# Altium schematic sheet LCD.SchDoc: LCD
size A4; Date: Not used; ApprovedBy: Not used; CheckedBy: Not used; Author: Not used; CompanyName: STMicroelectronics; DrawnBy: Not used; Engineer: Not used; Organization: Not used; Address1: Not used; Address2: Not used; Address3: Not used; Address4: Not used; DocumentNumber: Not used; Revision: Not used; SheetNumber: 13; SheetTotal: 23
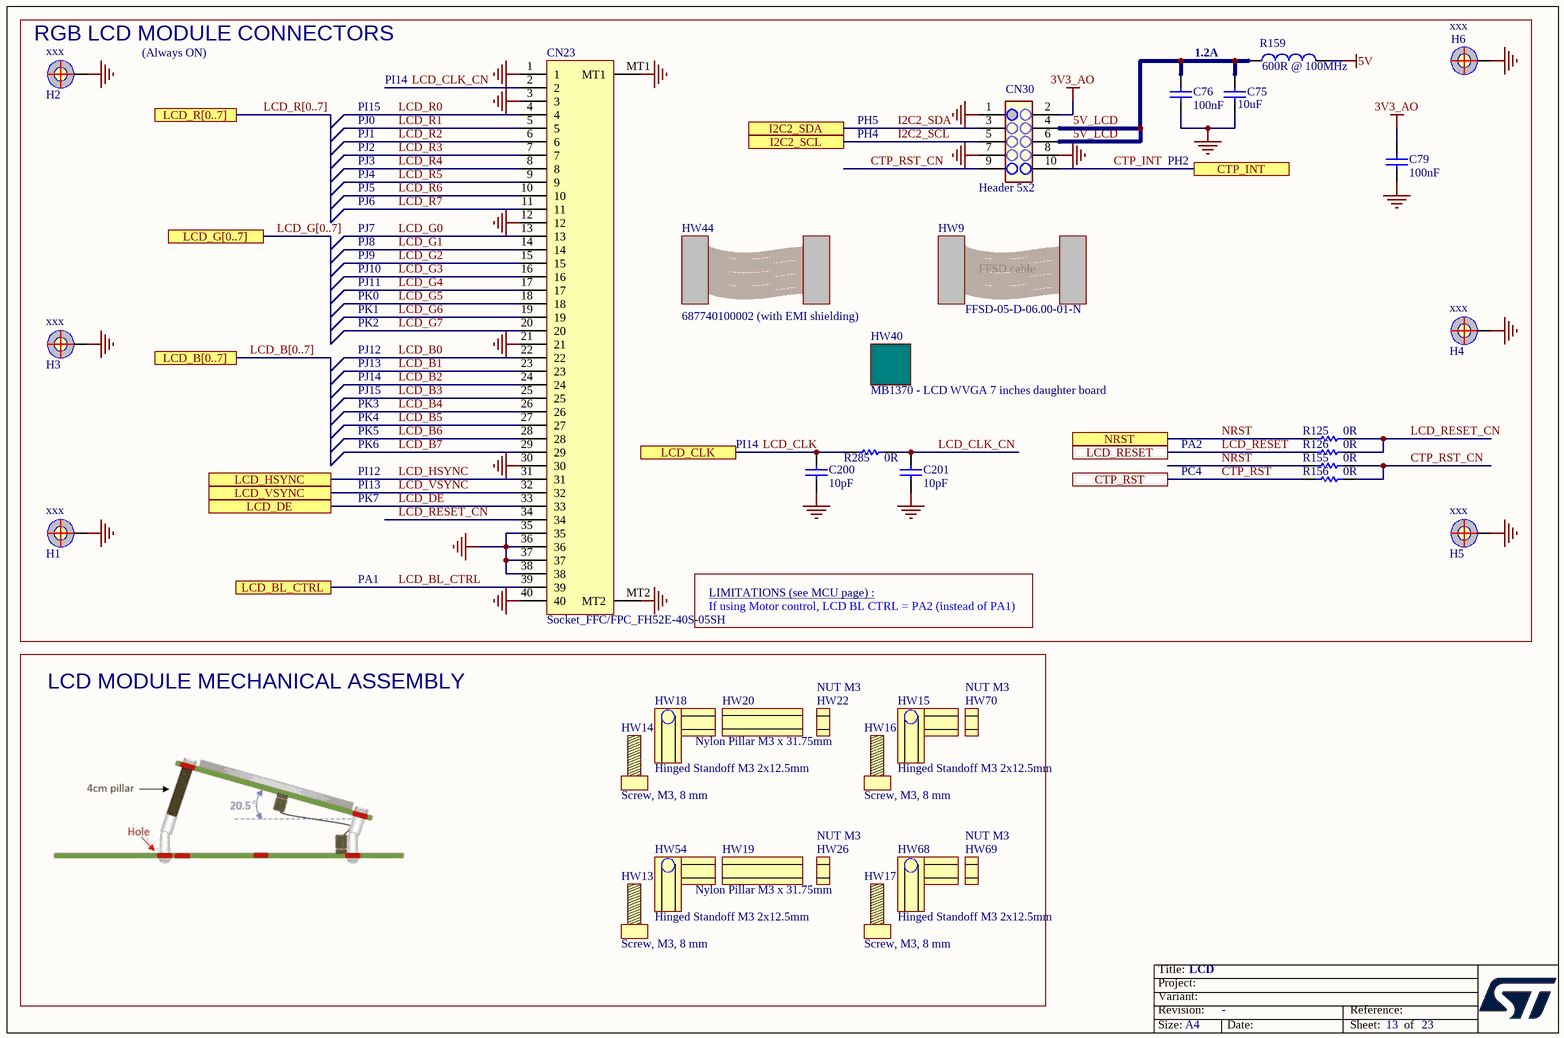
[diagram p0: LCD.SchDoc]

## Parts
C75  value 10uF  [C0805]  (hidden comment: Capacitor)
C76  value 100nF  [C0402]  (hidden comment: Capacitor)
C79  value 100nF  [C0402]  (hidden comment: Capacitor)
C200  value 10pF  [C0402]  (hidden comment: Capacitor)
C201  value 10pF  [C0402]  (hidden comment: Capacitor)
CN23  value Socket_FFC/FPC_FH52E-40S-05SH  [CON_HRS_FH52E-40S-05SH]  (hidden comment: FH52E-40S-0.5SH)
CN30  value Header 5x2  [CON_SAMTEC_FTSH-105-01-L-DV-K]  (hidden comment: Header 5x2 Generic)
H1  value xxx  [PTH_M1261-3005-N_3P5X6_M3_H14]  (hidden comment: POSITION HOLE)  (no BOM)
H2  value xxx  [PTH_M1261-3005-N_3P5X6_M3_H14]  (hidden comment: POSITION HOLE)  (no BOM)
H3  value xxx  [PTH_M1261-3005-N_3P5X6_M3_H14]  (hidden comment: POSITION HOLE)  (no BOM)
H4  value xxx  [PTH_M1261-3005-N_3P5X6_M3_H14]  (hidden comment: POSITION HOLE)  (no BOM)
H5  value xxx  [PTH_M1261-3005-N_3P5X6_M3_H14]  (hidden comment: POSITION HOLE)  (no BOM)
H6  value xxx  [PTH_M1261-3005-N_3P5X6_M3_H14]  (hidden comment: POSITION HOLE)  (no BOM)
HW9  value FFSD-05-D-06.00-01-N  (hidden comment: FFSD05_CABLE)  (mechanical)
HW13  value Screw, M3, 8 mm  (hidden comment: SCREW)  (no BOM)
HW14  value Screw, M3, 8 mm  (hidden comment: SCREW)  (no BOM)
HW15  value Hinged Standoff M3 2x12.5mm  (hidden comment: Hinged_Standoff)  (no BOM)
HW16  value Screw, M3, 8 mm  (hidden comment: SCREW)  (no BOM)
HW17  value Screw, M3, 8 mm  (hidden comment: SCREW)  (no BOM)
HW18  value Hinged Standoff M3 2x12.5mm  (hidden comment: Hinged_Standoff)  (no BOM)
HW19  value Nylon Pillar M3 x 31.75mm  (hidden comment: PILLAR)  (no BOM)
HW20  value Nylon Pillar M3 x 31.75mm  (hidden comment: PILLAR)  (no BOM)
HW22  value NUT M3  (hidden comment: NUT)  (no BOM)
HW26  value NUT M3  (hidden comment: NUT)  (no BOM)
HW40  value MB1370 - LCD WVGA 7 inches daughter board  [LCD_DRAWING_ROCKTEK_RK070ER9427L]  (hidden comment: Daughter_Board)
HW44  value 687740100002 (with EMI shielding)  (hidden comment: CABLE)  (mechanical)
HW54  value Hinged Standoff M3 2x12.5mm  (hidden comment: Hinged_Standoff)  (no BOM)
HW68  value Hinged Standoff M3 2x12.5mm  (hidden comment: Hinged_Standoff)  (no BOM)
HW69  value NUT M3  (hidden comment: NUT)  (no BOM)
HW70  value NUT M3  (hidden comment: NUT)  (no BOM)
R125  value 0R  [R0603]  (hidden comment: Resistor)
R126  value 0R  [R0603]  (hidden comment: Resistor)
R155  value 0R  [R0603]  (hidden comment: Resistor)
R156  value 0R  [R0603]  (hidden comment: Resistor)
R159  value 600R @ 100MHz  [IND_0603_H0P8]  (hidden comment: Inductor)
R285  value 0R  [R0603]  (hidden comment: Resistor)

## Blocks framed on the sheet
RGB LCD MODULE CONNECTORS: C75 C76 C79 C200 C201 CN23 CN30 H1-H6 HW9 HW40 HW44 R125 R126 R155 R156 R159 R285
LCD MODULE MECHANICAL ASSEMBLY: HW13-HW20 HW22 HW26 HW54 HW68-HW70

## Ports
CTP_INT, CTP_RST, I2C2_SCL, I2C2_SDA, LCD_B[0..7], LCD_BL_CTRL, LCD_CLK, LCD_DE, LCD_G[0..7], LCD_HSYNC, LCD_R[0..7], LCD_RESET, LCD_VSYNC, NRST

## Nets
3V3_AO: C79.2 CN30.2
5V: R159.2
GND: C75.1 C76.2 C79.1 C200.1 C201.1 CN23.1 CN23.3 CN23.12 CN23.21 CN23.30 CN23.35 CN23.36 CN23.37 CN23.38 CN23.40 CN23.MT1 CN23.MT2 CN30.1 CN30.7 CN30.8 H1.1 H2.1 H3.1 H4.1 H5.1 H6.1
5V_LCD: C75.2 C76.1 CN30.4 CN30.6 R159.1
CTP_INT: CN30.10 ; port CTP_INT
CTP_RST: R156.1 ; port CTP_RST
CTP_RST_CN: CN30.9 R155.2 R156.2
I2C2_SCL: CN30.5 ; port I2C2_SCL
I2C2_SDA: CN30.3 ; port I2C2_SDA
LCD_B0: CN23.22
LCD_B1: CN23.23
LCD_B2: CN23.24
LCD_B3: CN23.25
LCD_B4: CN23.26
LCD_B5: CN23.27
LCD_B6: CN23.28
LCD_B7: CN23.29
LCD_BL_CTRL: CN23.39 ; port LCD_BL_CTRL
LCD_CLK: C200.2 R285.1 ; port LCD_CLK
LCD_CLK_CN: C201.2 CN23.2 R285.2
LCD_DE: CN23.33 ; port LCD_DE
LCD_G0: CN23.13
LCD_G1: CN23.14
LCD_G2: CN23.15
LCD_G3: CN23.16
LCD_G4: CN23.17
LCD_G5: CN23.18
LCD_G6: CN23.19
LCD_G7: CN23.20
LCD_HSYNC: CN23.31 ; port LCD_HSYNC
LCD_R0: CN23.4
LCD_R1: CN23.5
LCD_R2: CN23.6
LCD_R3: CN23.7
LCD_R4: CN23.8
LCD_R5: CN23.9
LCD_R6: CN23.10
LCD_R7: CN23.11
LCD_RESET: R126.1 ; port LCD_RESET
LCD_RESET_CN: CN23.34 R125.2 R126.2
LCD_VSYNC: CN23.32 ; port LCD_VSYNC
NRST: R125.1 R155.1 ; port NRST

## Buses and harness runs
bus LCD_B[0..7] = port LCD_B[0..7]
bus LCD_G[0..7] = port LCD_G[0..7]
bus LCD_R[0..7] = port LCD_R[0..7]

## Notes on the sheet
- (Always ON)
- PI15
- PI14
- 1.2A
- PJ0
- PJ1
- PJ2
- PJ3
- PJ4
- PH5
- PH4
- PH2
- PJ5
- PJ6
- PJ7
- PJ8
- PJ9
- PJ10
- PJ11
- PK0
- PK1
- PK2
- PJ12
- PJ13
- PJ14
- PJ15
- PK3
- PK4
- PK5
- PK6
- PA2
- PI12
- PI13
- PK7
- PC4
- PA1
- LIMITATIONS (see MCU page) :
- If using Motor control, LCD BL CTRL = PA2 (instead of PA1)

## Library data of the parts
C75 = MCD-00014: Capacitor, MLCC, 10uF, 25V, X5R, 10%, 0805, T=0,85mm; Manufacturer_Part_Number: CC0805KRX5R8BB106; Manufacturer: YAGEO; Full_Alternate_Internal_Part_Number: MCD-02385; Part_Preference: Recommended; Partial_Alternate_Internal_Part_Number: MCD-03053; Provided_By: SUBCO; ECCN_US: EAR99; ECCN_EU: NEC; Component_Country_Of_Origin: China; ID: 2468; ShowFields: YES
C76 C79 = MCD-00006: Capacitor, MLCC, 100nF, 16V, X7R, 10%, 0402, T=0.5mm; Manufacturer_Part_Number: CC0402KRX7R7BB104; Manufacturer: YAGEO; Alternate_Manufacturer_Part_Number: GCM155R71C104KA55D; Alternate_Manufacturer: MURATA; Part_Preference: Recommended; Partial_Alternate_Internal_Part_Number: MCD-03299; Provided_By: SUBCO; ECCN_US: EAR99; ECCN_EU: NEC; Component_Country_Of_Origin: China; ID: 2474; Order_Code_RS: 9402047; ShowFields: YES
C200 C201 = MCD-00015: Capacitor, MLCC, 10pF, 50V, NPO, 5%, 0402, T=0,5mm; Manufacturer_Part_Number: CC0402JRNPO9BN100; Manufacturer: YAGEO; Part_Preference: Recommended; ECCN_US: EAR99; ECCN_EU: NEC; Provided_By: SUBCO; Component_Country_Of_Origin: China; ID: 2465; Order_Code_RS: 3019160RL; ShowFields: YES
CN23 = MCD-01992: FFC et FPC connector 0.5MM 40P LNG MTL FITNG SMT VERT MNT; Manufacturer_Part_Number: FH52E-40S-05SH; Manufacturer: HIROSE; Part_Preference: Recommended; ECCN_US: EAR99; ECCN_EU: NEC; Provided_By: SUBCO; Component_Country_Of_Origin: Japan; ID: 4092; ShowFields: YES
CN30 = MCD-00610: Surface mount, vertical male connector. Double row of 5 pins, 1.27mm pitch, 3.05mm lead. Mates with FFSD connector; Manufacturer_Part_Number: FTSH-105-01-L-DV-K; Manufacturer: SAMTEC; Alternate_Manufacturer_Part_Number: P127B-2x05MGF-079-1A; Alternate_Manufacturer: JIUBABA; Part_Preference: Recommended; Provided_By: SUBCO; Component_Country_Of_Origin: China, Costa Rica, Malaysia, USA, Vietnam; ID: 3134; Order_Code_RS: 159-2365; ShowFields: YES
H1-H6 = MCD-00035: POSITION HOLE C6D3R5; Part_Type: Misc; Part_Preference: Recommended; Component_Country_Of_Origin: Unknown; ID: 2482; ShowFields: YES
HW9 = MCD-00612: FFSD series Ribbon cable pitch1.27mm 5pin x 2row, 15cm length.; Part_Type: Misc; Manufacturer: SAMTEC; Part_Preference: Recommended; ECCN_US: EAR99; ECCN_EU: NEC; Provided_By: SUBCO; Component_Country_Of_Origin: China, Costa Rica, Malaysia, USA, Vietnam; ID: 3133; Order_Code_RS: 901-1683; ShowFields: YES
HW13 HW14 HW16 HW17 = MCD-01711: Screw, M3, 8 mm, Stainless Steel; Part_Type: Accessory; Manufacturer: ETTINGER; Part_Preference: Forbidden; Provided_By: SUBCO; Component_Country_Of_Origin: Unknown; ID: 3811; ShowFields: YES
HW15 HW18 HW54 HW68 = MCD-01710: M3 2x12.5mm male to female Hinged Hex Standoff made of brass with nickel plated finish; Part_Type: Accessory; Manufacturer: ETTINGER; Alternate_Manufacturer_Part_Number: 14.04.3.00034; Alternate_Manufacturer: JIUBABA; Part_Preference: Forbidden; Provided_By: SUBCO; Component_Country_Of_Origin: Unknown; ID: 3810; ShowFields: YES
HW19 HW20 = MCD-01841: Nylon Pillar M3 x 31.75mm Male/Female; Part_Type: Accessory; Manufacturer_Part_Number: 4820; Manufacturer: KEYSTONE ELECTRONICS; Part_Preference: Forbidden; ECCN_US: EAR99; ECCN_EU: NEC; Provided_By: SUBCO; Component_Country_Of_Origin: USA; ID: 3941; ShowFields: YES
HW22 HW26 HW69 HW70 = MCD-01354: Nut, Steel, M3; Part_Type: Accessory; Manufacturer_Part_Number: 1110030; Manufacturer: DURATOOL; Manufacturer_HQ_COO: Unknown; Part_Preference: Forbidden; Component_Country_Of_Origin: Germany; ID: 3454; ShowFields: YES
HW40 = MCD-01035: MB1370 - LCD WVGA 7 inches daughter board; Part_Type: Misc; Manufacturer: STMICROELECTRONICS; Manufacturer_HQ_COO: EU; Part_Preference: Recommended; Provided_By: SUBCO with ST control; Component_Country_Of_Origin: Unknown; ID: 2986; ShowFields: YES
HW44 = MCD-02049: FFC/FPC Flex Cable, Opposite Side Contacts, WR-FFC 0.5mm Type 2 40P 100mm length, customized with EMI shielding; Part_Type: Accessory; Manufacturer: WURTH ELEKTRONIK; Part_Preference: Recommended; Order_Code_RS: 1222740; ECCN_US: EAR99; ECCN_EU: NEC; Provided_By: SUBCO; Component_Country_Of_Origin: China; ID: 4149; ShowFields: YES
R125 R126 R155 R156 R285 = MCD-00056: Resistor,0R,0603,5%,1/10W; Manufacturer_Part_Number: RC0603JR-070RL; Manufacturer: YAGEO; Part_Preference: Recommended; Provided_By: SUBCO; ECCN_US: EAR99; ECCN_EU: NEC; Component_Country_Of_Origin: China; ID: 2536; Order_Code_RS: 9233130RL; ShowFields: YES
R159 = MCD-00593: Ferrite bead, 600R @ 100MHz,  1.3A, 150mOhm, 0603; Manufacturer_Part_Number: BLM18KG601SN1D; Manufacturer: MURATA; Part_Preference: Recommended; ECCN_US: EAR99; ECCN_EU: NEC; Provided_By: SUBCO; Component_Country_Of_Origin: Japan°°; ID: 3152; Order_Code_RS: 167-4203; ShowFields: YES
